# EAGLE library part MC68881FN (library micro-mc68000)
68xxx PROCESSOR
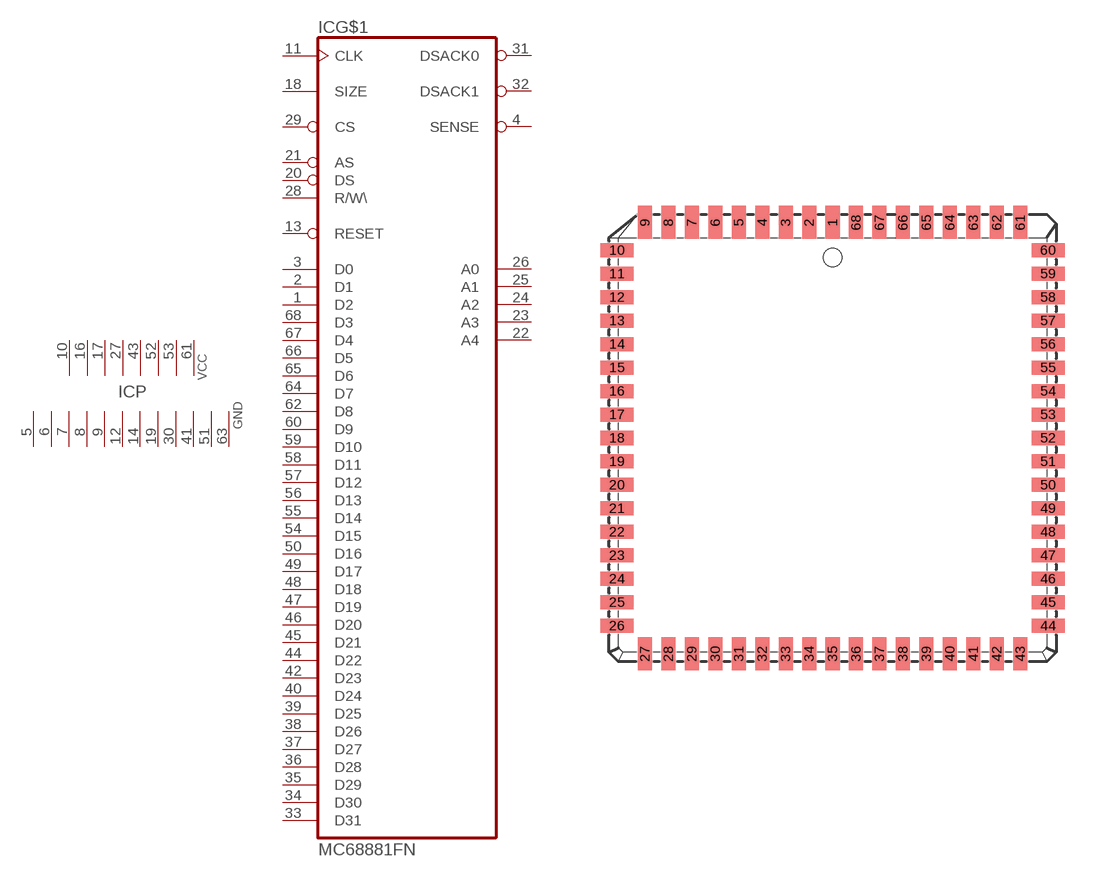
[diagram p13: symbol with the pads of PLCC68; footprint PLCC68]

Designator prefix IC; gates G$1=68881 P=8PWR12GN

## MC68881FN  [PLCC68]
1  G$1:D2
2  G$1:D1
3  G$1:D0
4  G$1:SENSE
5  P:GND  pwr
6  P:GND  pwr
7  P:GND  pwr
8  P:GND  pwr
9  P:GND  pwr
10  P:VCC  pwr
11  G$1:CLK  in
12  P:GND  pwr
13  G$1:RESET  in
14  P:GND  pwr
16  P:VCC  pwr
17  P:VCC  pwr
18  G$1:SIZE  in
19  P:GND  pwr
20  G$1:DS  in
21  G$1:AS  in
22  G$1:A4  in
23  G$1:A3  in
24  G$1:A2  in
25  G$1:A1  in
26  G$1:A0  in
27  P:VCC  pwr
28  G$1:R/W\  in
29  G$1:CS  in
30  P:GND  pwr
31  G$1:DSACK0  out
32  G$1:DSACK1  out
33  G$1:D31
34  G$1:D30
35  G$1:D29
36  G$1:D28
37  G$1:D27
38  G$1:D26
39  G$1:D25
40  G$1:D24
41  P:GND  pwr
42  G$1:D23
43  P:VCC  pwr
44  G$1:D22
45  G$1:D21
46  G$1:D20
47  G$1:D19
48  G$1:D18
49  G$1:D17
50  G$1:D16
51  P:GND  pwr
52  P:VCC  pwr
53  P:VCC  pwr
54  G$1:D15
55  G$1:D14
56  G$1:D13
57  G$1:D12
58  G$1:D11
59  G$1:D10
60  G$1:D9
61  P:VCC  pwr
62  G$1:D8
63  P:GND  pwr
64  G$1:D7
65  G$1:D6
66  G$1:D5
67  G$1:D4
68  G$1:D3

## Footprint PLCC68 (pad centres in mm)
PLASTIC LEADED CHIP CARRIER square
smd 0.76 x 1.8: 1 0,11.67; 2 -1.27,11.67; 3 -2.54,11.67; 4 -3.81,11.67; 5 -5.08,11.67; 6 -6.35,11.67; 7 -7.62,11.67; 8 -8.89,11.67; 9 -10.16,11.67; 27 -10.16,-11.67; 28 -8.89,-11.67; 29 -7.62,-11.67; 30 -6.35,-11.67; 31 -5.08,-11.67; 32 -3.81,-11.67; 33 -2.54,-11.67; 34 -1.27,-11.67; 35 0,-11.67; 36 1.27,-11.67; 37 2.54,-11.67; 38 3.81,-11.67; 39 5.08,-11.67; 40 6.35,-11.67; 41 7.62,-11.67; 42 8.89,-11.67; 43 10.16,-11.67; 61 10.16,11.67; 62 8.89,11.67; 63 7.62,11.67; 64 6.35,11.67; 65 5.08,11.67; 66 3.81,11.67; 67 2.54,11.67; 68 1.27,11.67
smd 1.8 x 0.76: 10 -11.67,10.16; 11 -11.67,8.89; 12 -11.67,7.62; 13 -11.67,6.35; 14 -11.67,5.08; 15 -11.67,3.81; 16 -11.67,2.54; 17 -11.67,1.27; 18 -11.67,0; 19 -11.67,-1.27; 20 -11.67,-2.54; 21 -11.67,-3.81; 22 -11.67,-5.08; 23 -11.67,-6.35; 24 -11.67,-7.62; 25 -11.67,-8.89; 26 -11.67,-10.16; 44 11.67,-10.16; 45 11.67,-8.89; 46 11.67,-7.62; 47 11.67,-6.35; 48 11.67,-5.08; 49 11.67,-3.81; 50 11.67,-2.54; 51 11.67,-1.27; 52 11.67,0; 53 11.67,1.27; 54 11.67,2.54; 55 11.67,3.81; 56 11.67,5.08; 57 11.67,6.35; 58 11.67,7.62; 59 11.67,8.89; 60 11.67,10.16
